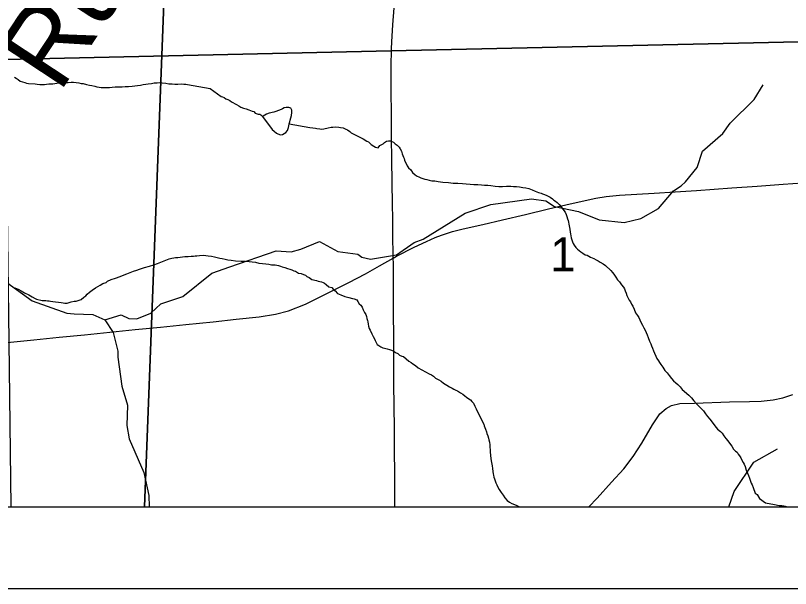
# Model space of a CAD drawing. Extents: x -6.1 to 38, y -7.7 to 22.
# Drawn here: x 7.096 to 8.043, y 14 to 14.701 of the extents above; entities that cross this region are included whole.
import ezdxf

# ---------------------------------------------------------------- set-up
doc = ezdxf.new("R2010")
doc.units = 0
for name, color, linetype in [('GM_X_Corporation', 7, 'Continuous'), ('GM_X_County_Road', 7, 'Continuous'), ('GM_X_Minor_Lake', 7, 'Continuous'), ('GM_X_Minor_River', 7, 'Continuous'), ('GM_X_Minor_River_Text', 7, 'Continuous'), ('GM_X_Section_Text', 7, 'Continuous'), ('GM_X_Township_Road', 7, 'Continuous'), ('SH_Data', 7, 'Continuous')]:
    doc.layers.add(name, color=color, linetype=linetype)

msp = doc.modelspace()

# ---------------------------------------------------------------- linework, layer by layer
at = {"layer": 'GM_X_Corporation'}
for points in [[(8.9, 14.68725), (8.9, 19.53649), (8.77571, 19.53237), (8.77312, 19.53228), (6.99327, 19.47331), (6.99349, 19.46054), (7.03821, 16.8882), (7.05054, 16.17866), (7.07262, 15.21743), (7.07601, 15.03919), (7.07603, 15.03845), (7.07902, 14.88093), (7.08348, 14.64684), (7.55487, 14.65733), (8.5875, 14.68029)], [(3.19219, 14.1), (8.25437, 14.1), (8.26188, 14.35188), (8.27757, 14.87811), (8.1023, 14.88375), (7.88923, 14.89059), (7.27984, 14.90301), (6.7864, 14.92029), (6.27951, 14.93803), (5.74746, 14.95956), (5.18977, 14.97327), (5.0967, 14.97556), (4.28061, 14.99995), (4.24786, 15.00093), (3.22473, 15.03847), (3.22164, 14.89402), (3.20818, 14.53184), (3.19363, 14.14313)], [(6.25814, 14.1), (7.25364, 14.1), (7.28457, 14.90716), (7.22185, 14.91015), (6.83138, 14.92264), (6.46239, 14.93366), (6.28581, 14.93893)], [(7.25364, 14.1), (8.25716, 14.1), (8.27613, 14.8776), (7.89065, 14.88943), (7.58452, 14.89838), (7.28457, 14.90716)], [(7.09053, 14.1), (8.9, 14.1), (8.9, 14.68725), (8.5875, 14.68029), (7.55487, 14.65733), (7.08348, 14.64684), (7.08792, 14.30249), (7.08793, 14.30152)]]:
    msp.add_lwpolyline(points, close=True, dxfattribs=at)
at = {"layer": 'GM_X_County_Road'}
for points in [[(7.55551, 14.65997), (7.55593, 14.66828), (7.5572, 14.6891), (7.55845, 14.70992)], [(7.55937, 14.1), (7.55935, 14.10976), (7.55926, 14.13917), (7.55904, 14.17024), (7.55884, 14.19628), (7.55865, 14.22232), (7.55841, 14.25116), (7.55818, 14.27999), (7.55809, 14.31106), (7.55802, 14.33328), (7.55795, 14.3555), (7.55784, 14.37646), (7.55772, 14.39742), (7.55757, 14.40398), (7.55716, 14.43504), (7.55694, 14.4524), (7.55672, 14.46976), (7.55633, 14.49686), (7.55587, 14.5243), (7.55541, 14.55175), (7.55528, 14.5801), (7.55515, 14.60844), (7.55505, 14.63792), (7.55551, 14.65997)], [(7.55757, 14.40398), (7.56158, 14.40645), (7.58306, 14.41728), (7.59806, 14.42449), (7.60886, 14.42935), (7.6163, 14.43206), (7.63007, 14.43639), (7.64284, 14.43962), (7.66687, 14.44516), (7.6909, 14.45069), (7.71911, 14.4574), (7.74731, 14.46411), (7.76839, 14.46914), (7.78837, 14.47377), (7.80481, 14.47737), (7.81741, 14.47929), (7.8338, 14.48091), (7.85506, 14.48226), (7.87631, 14.48362), (7.90205, 14.4851), (7.92778, 14.48659), (7.94945, 14.48821), (7.97112, 14.48982), (8.0021, 14.4921), (8.01792, 14.49325), (8.03374, 14.49442), (8.05739, 14.49599)], [(7.08591, 14.30068), (7.10229, 14.30238), (7.11868, 14.30408), (7.14958, 14.30721), (7.18049, 14.31035), (7.2114, 14.31348), (7.2423, 14.31662), (7.27321, 14.31975), (7.30412, 14.32289), (7.32086, 14.32458), (7.33759, 14.32628), (7.3657, 14.3293), (7.39382, 14.33232), (7.41388, 14.33551), (7.42975, 14.3397), (7.45013, 14.34788), (7.46661, 14.35588), (7.4831, 14.36388), (7.50328, 14.37436), (7.52346, 14.38483), (7.54052, 14.3944), (7.55757, 14.40398)]]:
    msp.add_lwpolyline(points, dxfattribs=at)
at = {"layer": 'GM_X_Minor_Lake'}
for points in [[(7.43351, 14.58199), (7.43344, 14.58503), (7.43225, 14.58728), (7.42995, 14.58837), (7.42691, 14.5883), (7.42425, 14.58787), (7.42238, 14.58669), (7.42049, 14.58589), (7.41747, 14.58468), (7.41408, 14.58309), (7.41181, 14.58266), (7.40575, 14.58138), (7.40273, 14.58018), (7.40048, 14.57899), (7.39861, 14.57743), (7.39786, 14.57703)], [(7.39786, 14.57703), (7.4096, 14.56133), (7.41193, 14.5591), (7.41502, 14.55688), (7.41925, 14.5547), (7.42229, 14.55514), (7.42642, 14.55751), (7.42826, 14.56021), (7.42971, 14.56366), (7.43004, 14.56595), (7.43038, 14.56824), (7.43109, 14.57054), (7.43142, 14.57282), (7.4325, 14.57551), (7.4332, 14.57856), (7.43351, 14.58199), (7.43344, 14.58503), (7.43225, 14.58728), (7.42995, 14.58837), (7.42691, 14.5883), (7.42425, 14.58787), (7.42238, 14.58669), (7.42049, 14.58589), (7.41747, 14.58468), (7.41408, 14.58309), (7.41181, 14.58266), (7.40575, 14.58138), (7.40273, 14.58018), (7.40048, 14.57899), (7.39861, 14.57743), (7.39786, 14.57703)], [(7.39786, 14.57703), (7.4096, 14.56133), (7.41193, 14.5591), (7.41502, 14.55688), (7.41925, 14.5547), (7.42229, 14.55514), (7.42642, 14.55751), (7.42826, 14.56021), (7.42971, 14.56366), (7.43004, 14.56595), (7.43038, 14.56824), (7.43109, 14.57054), (7.43142, 14.57282), (7.4325, 14.57551), (7.4332, 14.57856), (7.43351, 14.58199)]]:
    msp.add_lwpolyline(points, dxfattribs=at)
at = {"layer": 'GM_X_Minor_River'}
for points in [[(7.09509, 14.62535), (7.09702, 14.62386), (7.09932, 14.62238), (7.10201, 14.62053), (7.10469, 14.61944), (7.10736, 14.61872), (7.10966, 14.618), (7.11194, 14.61767), (7.12031, 14.61705), (7.12259, 14.61672), (7.12564, 14.61639), (7.12867, 14.61644), (7.13133, 14.61649), (7.13399, 14.61654), (7.13702, 14.61697), (7.13967, 14.61702), (7.14157, 14.61706), (7.14422, 14.61749), (7.14649, 14.6179), (7.14915, 14.61833), (7.1518, 14.61838), (7.15445, 14.61881), (7.15711, 14.61886), (7.16053, 14.61892), (7.16394, 14.61898), (7.16698, 14.61904), (7.1704, 14.61872)], [(7.1704, 14.61872), (7.17345, 14.61839), (7.1765, 14.61769), (7.17878, 14.61735), (7.18298, 14.61628), (7.18641, 14.61558), (7.18946, 14.61488), (7.19289, 14.61418), (7.19556, 14.61347), (7.19823, 14.61313), (7.20089, 14.6128), (7.20431, 14.61248), (7.20773, 14.61254), (7.21077, 14.6126), (7.21418, 14.61304), (7.21797, 14.61349), (7.22252, 14.61357), (7.22632, 14.61364), (7.23011, 14.61371), (7.23429, 14.61378), (7.23846, 14.61424), (7.24187, 14.61468), (7.24528, 14.61512), (7.24869, 14.61556), (7.25209, 14.61638), (7.25512, 14.61682), (7.25815, 14.61725), (7.26232, 14.61771), (7.26536, 14.61814), (7.26915, 14.61821), (7.27218, 14.61865), (7.27522, 14.61832), (7.27979, 14.61802), (7.28322, 14.61732), (7.2874, 14.61702), (7.29082, 14.6167), (7.29424, 14.61676), (7.29879, 14.61722), (7.30183, 14.6169), (7.30412, 14.61656), (7.30602, 14.61621), (7.33381, 14.61128)], [(7.20537, 14.32865), (7.22498, 14.33475), (7.23443, 14.33022), (7.24425, 14.32986), (7.2616, 14.33672), (7.27365, 14.34811), (7.30043, 14.35726), (7.33585, 14.38576), (7.35772, 14.39338), (7.41468, 14.41282), (7.4328, 14.41172), (7.4445, 14.41477), (7.4675, 14.42429), (7.4898, 14.41221), (7.51435, 14.40885), (7.51927, 14.40507), (7.52985, 14.40281), (7.56154, 14.40818), (7.58302, 14.423), (7.59396, 14.42719), (7.64522, 14.45912), (7.67653, 14.46941), (7.72634, 14.4767), (7.74408, 14.47408), (7.75467, 14.46728), (7.78376, 14.46089), (7.80907, 14.4507), (7.83966, 14.44772), (7.86003, 14.45231), (7.88152, 14.46485), (7.89996, 14.4861), (7.90938, 14.49256), (7.91465, 14.49712), (7.92857, 14.51496), (7.93532, 14.53467), (7.96018, 14.55632), (7.9692, 14.56884), (7.9982, 14.59807), (8.00948, 14.6159)], [(7.33381, 14.61128), (7.34712, 14.60177), (7.34904, 14.60105), (7.35095, 14.60033), (7.35289, 14.59885), (7.35557, 14.59777), (7.35788, 14.59668), (7.35981, 14.5952), (7.36597, 14.59192), (7.36905, 14.59008), (7.37136, 14.58862), (7.37443, 14.58754), (7.37787, 14.58648), (7.38094, 14.5854), (7.38324, 14.58469), (7.38516, 14.5836), (7.38707, 14.58326), (7.38901, 14.5814), (7.39247, 14.57996), (7.39475, 14.58), (7.39591, 14.57927), (7.39786, 14.57703)], [(7.43038, 14.56824), (7.45557, 14.56385), (7.45939, 14.56317), (7.46244, 14.56286), (7.46435, 14.56252), (7.46778, 14.56221), (7.47007, 14.56188), (7.47273, 14.56194), (7.47803, 14.56319), (7.48182, 14.56404), (7.48372, 14.56408), (7.48751, 14.56454), (7.49094, 14.56424), (7.49323, 14.56391), (7.49629, 14.56321), (7.49975, 14.56177), (7.50167, 14.56067), (7.50437, 14.55883), (7.5063, 14.55735), (7.50862, 14.55588), (7.51093, 14.55479), (7.51746, 14.55151), (7.52092, 14.54969), (7.52516, 14.54712), (7.52709, 14.54602), (7.53057, 14.54306), (7.53367, 14.54084), (7.53597, 14.53975), (7.53903, 14.53906), (7.54125, 14.54177), (7.54501, 14.54375), (7.54688, 14.54531), (7.54913, 14.54688), (7.55179, 14.54732), (7.55369, 14.54736), (7.55598, 14.54665), (7.5579, 14.54593), (7.55985, 14.54369), (7.56216, 14.54222), (7.56488, 14.53962), (7.56606, 14.53775), (7.56765, 14.53474), (7.56847, 14.53172), (7.56928, 14.52946), (7.57008, 14.52758), (7.57089, 14.52569), (7.57131, 14.5238), (7.5745, 14.51665), (7.57607, 14.5144), (7.57879, 14.5118), (7.58114, 14.50881), (7.58424, 14.50584), (7.58656, 14.50437), (7.58886, 14.50328), (7.59117, 14.50219), (7.59346, 14.50148), (7.59615, 14.5004), (7.59844, 14.50007), (7.6015, 14.49938), (7.60456, 14.49868), (7.60836, 14.49838), (7.61256, 14.49772), (7.6179, 14.49707), (7.62514, 14.49647), (7.63086, 14.49583), (7.63657, 14.49558), (7.6419, 14.49532), (7.64648, 14.49465), (7.65143, 14.49438), (7.65601, 14.4941), (7.66096, 14.49383), (7.66515, 14.49354), (7.66896, 14.49324), (7.67314, 14.49333), (7.67658, 14.49265), (7.68192, 14.49201), (7.68649, 14.49172), (7.69106, 14.49144), (7.69599, 14.49193), (7.70094, 14.49204), (7.70437, 14.49173), (7.70818, 14.49144), (7.71161, 14.49113), (7.71581, 14.49046), (7.71962, 14.48978), (7.72306, 14.4891), (7.72728, 14.48767), (7.73074, 14.48585), (7.73495, 14.48442), (7.73802, 14.48334), (7.73994, 14.48262), (7.74224, 14.48192), (7.74493, 14.48045), (7.74915, 14.47865), (7.75186, 14.47642), (7.75379, 14.47495), (7.75573, 14.47347)], [(7.75573, 14.47347), (7.75766, 14.47199), (7.75999, 14.46976), (7.76272, 14.46678), (7.7639, 14.4649), (7.76586, 14.46229), (7.76743, 14.46004), (7.76862, 14.45741), (7.76944, 14.45476), (7.77026, 14.45212), (7.77107, 14.44986), (7.77149, 14.44797), (7.77192, 14.4457), (7.77235, 14.44343), (7.77277, 14.44154), (7.77319, 14.43926), (7.77365, 14.43585), (7.77408, 14.43358), (7.7745, 14.43131), (7.77494, 14.42866), (7.77575, 14.4264), (7.77657, 14.42376), (7.77737, 14.42187), (7.77855, 14.42), (7.78052, 14.417), (7.78246, 14.41514), (7.78478, 14.41329), (7.78671, 14.41181), (7.78904, 14.40997), (7.79174, 14.40812), (7.79441, 14.40742), (7.79634, 14.40633), (7.79827, 14.40523), (7.80056, 14.40452), (7.80249, 14.40342), (7.80518, 14.40196), (7.80787, 14.40087), (7.81019, 14.39902), (7.81404, 14.39683), (7.81674, 14.39499), (7.82334, 14.38867), (7.82529, 14.38643), (7.82686, 14.38419), (7.82922, 14.38082), (7.83157, 14.37745), (7.83391, 14.37484), (7.83626, 14.37147), (7.83861, 14.36848), (7.83979, 14.3666), (7.84061, 14.36396), (7.84181, 14.36133), (7.84301, 14.35831), (7.84461, 14.35493), (7.84579, 14.35267), (7.84736, 14.35043), (7.84856, 14.34779), (7.85014, 14.34517), (7.85173, 14.34178), (7.85335, 14.33726), (7.85571, 14.33389), (7.85728, 14.33126), (7.85886, 14.32863), (7.86007, 14.32562), (7.86205, 14.32186), (7.86363, 14.31886), (7.86522, 14.31585), (7.86642, 14.31322), (7.86762, 14.3102), (7.86883, 14.30681), (7.87044, 14.30266), (7.87204, 14.29928), (7.87286, 14.29664), (7.87405, 14.294), (7.87526, 14.29061), (7.87647, 14.28759), (7.87806, 14.28421), (7.87965, 14.2812), (7.88161, 14.27858), (7.8828, 14.27633), (7.88437, 14.27408), (7.88672, 14.27072), (7.88909, 14.26659), (7.8922, 14.26361), (7.89454, 14.26062), (7.89729, 14.25688), (7.90001, 14.2539), (7.90272, 14.25168), (7.90505, 14.24945), (7.90778, 14.24647), (7.91051, 14.24349), (7.91865, 14.23645), (7.92176, 14.23309), (7.9245, 14.22935), (7.928, 14.22563), (7.93111, 14.22265), (7.93422, 14.21968), (7.93656, 14.21707), (7.93891, 14.2137), (7.94126, 14.21033), (7.94438, 14.20698), (7.94712, 14.20324)], [(6.94722, 14.44634), (6.97588, 14.45626), (6.98874, 14.44795), (7.00011, 14.42864), (7.00541, 14.42638), (7.01486, 14.4192), (7.03337, 14.41393), (7.08557, 14.37425), (7.11659, 14.35158), (7.15891, 14.33651), (7.16797, 14.33577), (7.19063, 14.33506), (7.20537, 14.32865), (7.21522, 14.31313), (7.22094, 14.2904), (7.22096, 14.28282), (7.22596, 14.24759), (7.23281, 14.22411), (7.23212, 14.19948), (7.2348, 14.18319), (7.25303, 14.14192), (7.25914, 14.11389), (7.25945, 14.1)], [(7.20288, 14.37289), (7.20666, 14.37411), (7.20853, 14.37567), (7.21305, 14.37767), (7.21833, 14.37968), (7.224, 14.38171), (7.2289, 14.38371), (7.23229, 14.38493), (7.23606, 14.38653), (7.24022, 14.38814), (7.24437, 14.38937), (7.24739, 14.39058), (7.25381, 14.39262), (7.25986, 14.39427), (7.26515, 14.3959), (7.26968, 14.39752), (7.28364, 14.40315), (7.28704, 14.40398), (7.28932, 14.40441), (7.29159, 14.40484), (7.29425, 14.4049), (7.29729, 14.40534), (7.30298, 14.40585), (7.30716, 14.40594), (7.31058, 14.40639), (7.31362, 14.40646), (7.31551, 14.40688), (7.31741, 14.40692), (7.32083, 14.40738), (7.32577, 14.40749), (7.33149, 14.40685), (7.33568, 14.40656), (7.33912, 14.4055), (7.34256, 14.40481), (7.34562, 14.40412), (7.34868, 14.40342), (7.35212, 14.40274), (7.35556, 14.40205), (7.35937, 14.40138), (7.36471, 14.40073), (7.37157, 14.40012), (7.37652, 14.40023), (7.38147, 14.39996), (7.38528, 14.39966), (7.3891, 14.39898), (7.3933, 14.39794), (7.39788, 14.39728), (7.40207, 14.39699), (7.4055, 14.39668), (7.40894, 14.396), (7.41313, 14.39571), (7.41733, 14.39504), (7.41962, 14.39433), (7.42193, 14.39324), (7.42499, 14.39254), (7.42843, 14.39148), (7.43112, 14.3904), (7.4338, 14.3897), (7.43611, 14.38861), (7.43802, 14.38789), (7.44187, 14.38569), (7.44493, 14.385), (7.448, 14.38392), (7.45029, 14.38321), (7.45185, 14.38135), (7.45492, 14.38027), (7.45801, 14.37806), (7.46375, 14.37667), (7.46566, 14.37595), (7.46795, 14.37562), (7.46987, 14.3749), (7.47179, 14.37418), (7.4737, 14.37346), (7.47565, 14.37161), (7.47874, 14.36901), (7.48257, 14.36796), (7.48413, 14.36609), (7.48646, 14.36386), (7.48957, 14.36089), (7.49341, 14.35907), (7.4984, 14.3569), (7.50337, 14.35587), (7.50757, 14.35482), (7.50987, 14.35411), (7.51294, 14.35304), (7.51413, 14.35078), (7.51608, 14.34816), (7.51803, 14.34631), (7.5196, 14.34406), (7.52081, 14.34066), (7.5224, 14.33766), (7.52397, 14.33503), (7.52478, 14.33277), (7.52522, 14.33012), (7.52603, 14.32786), (7.52645, 14.32597), (7.52689, 14.32332), (7.52732, 14.32066), (7.52814, 14.31802), (7.52933, 14.31577), (7.53133, 14.31125)], [(7.09535, 14.36751), (7.09918, 14.36607), (7.10303, 14.36387), (7.10726, 14.36168), (7.11226, 14.35913), (7.1165, 14.35656), (7.11996, 14.35474), (7.12189, 14.35364), (7.12877, 14.35227), (7.13104, 14.35232), (7.13334, 14.35199), (7.13524, 14.35165), (7.13715, 14.35169), (7.13905, 14.35135), (7.14172, 14.35103), (7.14477, 14.35072), (7.14859, 14.35004), (7.15202, 14.34974), (7.15431, 14.34941), (7.15622, 14.34907), (7.15927, 14.34875), (7.16418, 14.35038), (7.16797, 14.35122), (7.17025, 14.35127), (7.17403, 14.3525), (7.17629, 14.35331), (7.17965, 14.35642), (7.1819, 14.35799), (7.18376, 14.35993), (7.18637, 14.36227), (7.18974, 14.365), (7.19386, 14.36775), (7.19687, 14.36934), (7.1995, 14.37091), (7.20288, 14.37289)], [(7.53133, 14.31125), (7.53291, 14.30825), (7.5345, 14.30524), (7.5353, 14.30336), (7.5365, 14.30072), (7.53807, 14.29848), (7.54, 14.297), (7.54231, 14.29553), (7.54462, 14.29444), (7.54692, 14.29373), (7.54997, 14.29304), (7.55303, 14.29234), (7.55533, 14.29163), (7.55725, 14.29053), (7.56034, 14.2887), (7.56303, 14.28724), (7.56535, 14.28539), (7.56804, 14.28431), (7.56996, 14.28359), (7.57654, 14.27803), (7.57923, 14.27657), (7.58156, 14.27472), (7.58465, 14.27251), (7.58812, 14.26992), (7.59236, 14.26736), (7.59698, 14.26479), (7.60121, 14.26261), (7.60429, 14.26115), (7.6066, 14.25969), (7.60932, 14.25708), (7.61316, 14.25527), (7.61624, 14.25343), (7.61895, 14.25121), (7.62281, 14.24864), (7.62628, 14.24643), (7.62936, 14.24498), (7.63166, 14.24389), (7.63398, 14.24242), (7.6359, 14.2417), (7.63975, 14.23912), (7.64245, 14.23766), (7.64477, 14.23581), (7.64709, 14.23396), (7.64979, 14.23212), (7.65173, 14.23064), (7.65367, 14.22879), (7.65562, 14.22655), (7.65721, 14.22316), (7.6588, 14.21977), (7.66041, 14.21601), (7.66199, 14.213), (7.66359, 14.20962), (7.66557, 14.20586), (7.66637, 14.20398), (7.66796, 14.20097), (7.66875, 14.19909), (7.66956, 14.19683), (7.67037, 14.19494), (7.67158, 14.19155), (7.672, 14.18966), (7.6732, 14.18665), (7.67402, 14.184), (7.67445, 14.18173), (7.67527, 14.17909), (7.67534, 14.17567), (7.67591, 14.16656), (7.67637, 14.16315), (7.67684, 14.1586), (7.6777, 14.15406), (7.67817, 14.14989), (7.67862, 14.14686), (7.67908, 14.14307), (7.67951, 14.14042), (7.67994, 14.13853), (7.68036, 14.13626), (7.68117, 14.13399), (7.68198, 14.13173), (7.6828, 14.12909), (7.68399, 14.12683), (7.68519, 14.12382), (7.68677, 14.12119), (7.68951, 14.11745), (7.69187, 14.11408), (7.69384, 14.11071), (7.69657, 14.10773), (7.69966, 14.10551), (7.70235, 14.10405), (7.70543, 14.1026), (7.70849, 14.10152), (7.71157, 14.10007), (7.71184, 14.1)], [(7.94712, 14.20324), (7.95025, 14.19913), (7.95377, 14.19465), (7.95725, 14.19206), (7.9592, 14.18982), (7.96117, 14.18682), (7.9639, 14.18346), (7.96625, 14.18047), (7.9682, 14.17786), (7.97095, 14.17412), (7.97331, 14.17037), (7.97564, 14.16814), (7.97757, 14.16666), (7.97876, 14.1644), (7.98033, 14.16216), (7.9819, 14.15991), (7.98349, 14.15691), (7.98506, 14.15428), (7.98625, 14.15203), (7.98745, 14.14939), (7.98869, 14.14486), (7.99029, 14.14109), (7.9915, 14.13808), (7.9927, 14.13506), (7.99352, 14.13242), (7.99474, 14.12865), (7.99592, 14.12677), (7.99713, 14.12338), (7.99956, 14.11659), (8.00187, 14.11512), (8.00502, 14.11025), (8.01237, 14.10471), (8.02306, 14.10266), (8.02879, 14.10164), (8.03222, 14.10134), (8.03451, 14.10101), (8.03642, 14.10067), (8.03898, 14.1)], [(7.96734, 14.1), (7.97375, 14.11868), (7.99782, 14.15434), (8.02685, 14.17069)]]:
    msp.add_lwpolyline(points, dxfattribs=at)
at = {"layer": 'GM_X_Township_Road'}
msp.add_lwpolyline([(7.7964, 14.1), (7.80659, 14.11058), (7.8242, 14.13012), (7.83915, 14.14651), (7.85072, 14.16123), (7.86134, 14.17787), (7.87436, 14.2003), (7.87895, 14.20753), (7.88328, 14.21357), (7.891, 14.22032), (7.89727, 14.22369), (7.90764, 14.22635), (7.92549, 14.22683), (7.96842, 14.22827), (7.99278, 14.22876), (8.00701, 14.229), (8.02173, 14.23069), (8.0333, 14.23334), (8.0456, 14.23744)], dxfattribs=at)
at = {"layer": 'SH_Data'}
for p, q in [((2.1, 14.1), (8.9, 14.1)), ((2, 14), (9, 14))]:
    msp.add_line(p, q, dxfattribs=at)

# ---------------------------------------------------------------- texts
at = {"layer": 'GM_X_Minor_River_Text'}
msp.add_text('Run', height=0.094679, rotation=56.5989, dxfattribs=at).set_placement((7.14955, 14.60465))
at = {"layer": 'GM_X_Section_Text'}
msp.add_text('1', height=0.04186, rotation=0.00001, dxfattribs=at).set_placement((7.74927, 14.38769))

doc.saveas('drawing.dxf')
